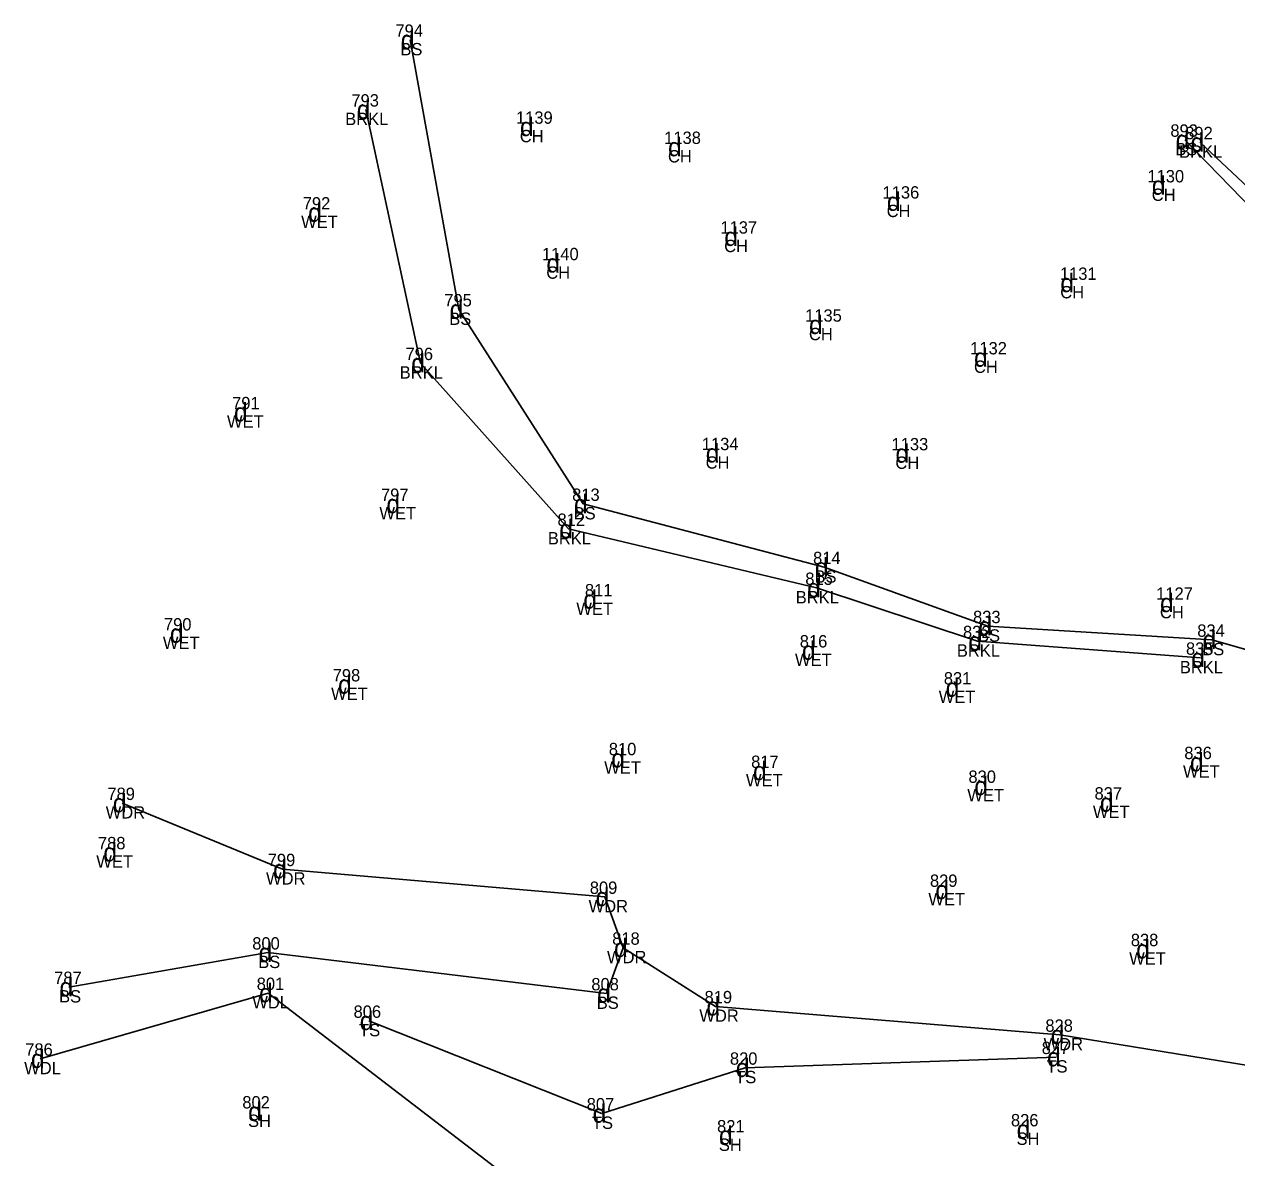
# Model space of a CAD drawing. Extents: x 17459 to 21139, y 33814 to 34251.
# Drawn here: x 17505 to 17701.5, y 34067.8 to 34251.5 of the extents above; entities that cross this region are included whole.
import ezdxf

# ---------------------------------------------------------------- set-up
doc = ezdxf.new("R2010")
doc.units = 0
for name, color, linetype in [('Level 14', 7, 'Continuous'), ('Level 16', 7, 'Continuous'), ('Level 17', 7, 'Continuous'), ('Level 46', 7, 'Continuous'), ('Level 47', 7, 'Continuous'), ('Level 48', 7, 'Continuous')]:
    doc.layers.add(name, color=color, linetype=linetype)

msp = doc.modelspace()

# ---------------------------------------------------------------- linework, layer by layer
at = {"layer": 'Level 14'}
for p, q in [((17520.81, 34125.28), (17546.8, 34114.57)), ((17546.8, 34114.57), (17599.08, 34110.07)), ((17599.08, 34110.07), (17602.06, 34101.83)), ((17602.06, 34101.83), (17617.03, 34092.34)), ((17507.54, 34083.85), (17544.51, 34094.5)), ((17544.51, 34094.5), (17594.09, 34056.45)), ((17617.03, 34092.34), (17672.83, 34087.73)), ((17672.83, 34087.73), (17725.88, 34079.05))]:
    msp.add_line(p, q, dxfattribs=at)
at = {"layer": 'Level 17'}
for p, q in [((17560.35, 34237.65), (17569.18, 34196.57)), ((17707.44, 34221.17), (17695.5, 34232.36)), ((17569.18, 34196.57), (17593.19, 34169.7)), ((17593.19, 34169.7), (17633.36, 34160.14)), ((17633.36, 34160.14), (17659.48, 34151.51)), ((17659.48, 34151.51), (17695.62, 34148.82))]:
    msp.add_line(p, q, dxfattribs=at)
at = {"layer": 'Level 48'}
for p, q in [((17567.49, 34248.95), (17575.41, 34205.27)), ((17706.46, 34218.93), (17693.09, 34232.76)), ((17575.41, 34205.27), (17595.57, 34173.75)), ((17595.57, 34173.75), (17634.61, 34163.5)), ((17634.61, 34163.5), (17661.12, 34153.94)), ((17661.12, 34153.94), (17697.45, 34151.73)), ((17697.45, 34151.73), (17739.75, 34139.78)), ((17599.32, 34094.44), (17602.06, 34101.83)), ((17512.17, 34095.47), (17544.44, 34101.05)), ((17544.44, 34101.05), (17599.32, 34094.44)), ((17560.83, 34089.99), (17598.57, 34074.99)), ((17621.79, 34082.39), (17672.24, 34084.12)), ((17598.57, 34074.99), (17621.79, 34082.39))]:
    msp.add_line(p, q, dxfattribs=at)

# ---------------------------------------------------------------- texts
at = {"layer": 'Level 16'}
for p in [(17550.97, 34219.47), (17538.95, 34187.1), (17563.66, 34172.25), (17595.57, 34156.78), (17528.56, 34151.25), (17631.01, 34148.5), (17555.82, 34143), (17654.31, 34142.5), (17600.1, 34131.04), (17693.9, 34130.41), (17623.08, 34128.98), (17658.95, 34126.56), (17679.3, 34123.86), (17517.78, 34115.8), (17652.63, 34109.71), (17685.18, 34100.1)]:
    msp.add_text('d', height=3, dxfattribs=at).set_placement(p)
at = {"layer": 'Level 46'}
for s, p in [('794', (17565.13, 34249.45)), ('BS', (17565.93, 34246.45)), ('793', (17557.99, 34238.15)), ('BRKL', (17556.99, 34235.15)), ('1139', (17584.67, 34235.36)), ('893', (17690.73, 34233.26)), ('CH', (17585.29, 34232.36)), ('1138', (17608.69, 34232.09)), ('892', (17693.14, 34232.86)), ('CH', (17609.3, 34229.09)), ('BS', (17691.53, 34230.26)), ('BRKL', (17692.15, 34229.86)), ('1130', (17687.01, 34225.86)), ('1136', (17644.08, 34223.24)), ('792', (17550.11, 34221.47)), ('CH', (17687.71, 34222.86)), ('CH', (17644.75, 34220.24)), ('WET', (17549.85, 34218.47)), ('1137', (17617.8, 34217.56)), ('1140', (17588.88, 34213.25)), ('CH', (17618.41, 34214.56)), ('CH', (17589.58, 34210.25)), ('1131', (17672.83, 34210.07)), ('795', (17573.05, 34205.77)), ('CH', (17672.88, 34207.07)), ('BS', (17573.85, 34202.77)), ('1135', (17631.53, 34203.29)), ('CH', (17632.15, 34200.29)), ('1132', (17658.29, 34197.99)), ('796', (17566.76, 34197.07)), ('BRKL', (17565.82, 34194.07)), ('CH', (17658.9, 34194.99)), ('791', (17538.66, 34189.1)), ('WET', (17537.83, 34186.1)), ('1134', (17614.79, 34182.47)), ('1133', (17645.54, 34182.44)), ('CH', (17615.41, 34179.47)), ('CH', (17646.16, 34179.44)), ('797', (17562.79, 34174.25)), ('813', (17593.77, 34174.25)), ('WET', (17562.53, 34171.25)), ('812', (17591.39, 34170.2)), ('BS', (17594.01, 34171.25)), ('BRKL', (17589.83, 34167.2)), ('814', (17632.82, 34164)), ('815', (17631.56, 34160.64)), ('BS', (17633.05, 34161)), ('811', (17595.84, 34158.78)), ('1127', (17688.43, 34158.22)), ('BRKL', (17630.01, 34157.64)), ('WET', (17594.45, 34155.78)), ('833', (17658.75, 34154.44)), ('CH', (17689.04, 34155.22)), ('790', (17527.61, 34153.25)), ('816', (17630.66, 34150.5)), ('832', (17657.12, 34152.01)), ('BS', (17659.56, 34151.44)), ('834', (17695.09, 34152.23)), ('WET', (17527.44, 34150.25)), ('BRKL', (17656.13, 34149.01)), ('835', (17693.26, 34149.32)), ('BS', (17695.89, 34149.23)), ('WET', (17629.89, 34147.5)), ('798', (17554.96, 34145)), ('831', (17654.01, 34144.5)), ('BRKL', (17692.27, 34146.32)), ('WET', (17554.7, 34142)), ('WET', (17653.19, 34141.5)), ('810', (17599.71, 34133.04)), ('817', (17622.78, 34130.98)), ('836', (17692.99, 34132.41)), ('WET', (17598.97, 34130.04)), ('WET', (17692.78, 34129.41)), ('WET', (17621.95, 34127.98)), ('830', (17658, 34128.56)), ('789', (17518.44, 34125.78)), ('WET', (17657.82, 34125.56)), ('837', (17678.44, 34125.86)), ('WET', (17678.18, 34122.86)), ('WDR', (17518.17, 34122.78)), ('788', (17516.91, 34117.8)), ('799', (17544.43, 34115.07)), ('WET', (17516.65, 34114.8)), ('WDR', (17544.16, 34112.07)), ('829', (17651.76, 34111.71)), ('809', (17596.63, 34110.57)), ('WDR', (17596.44, 34107.57)), ('WET', (17651.51, 34108.71)), ('800', (17541.92, 34101.55)), ('818', (17600.26, 34102.33)), ('838', (17684.32, 34102.1)), ('WDR', (17599.42, 34099.33)), ('BS', (17542.89, 34098.55)), ('WET', (17684.06, 34099.1)), ('787', (17509.81, 34095.97)), ('801', (17542.64, 34095)), ('808', (17596.88, 34094.94)), ('BS', (17510.61, 34092.97)), ('WDL', (17541.93, 34092)), ('BS', (17597.76, 34091.94)), ('819', (17615.23, 34092.84)), ('806', (17558.34, 34090.49)), ('WDR', (17614.39, 34089.84)), ('TS', (17559.24, 34087.49)), ('828', (17670.47, 34088.23)), ('786', (17505.12, 34084.35)), ('827', (17669.88, 34084.62)), ('WDR', (17670.19, 34085.23)), ('820', (17619.34, 34082.89)), ('TS', (17670.65, 34081.62)), ('WDL', (17504.95, 34081.35)), ('TS', (17620.2, 34079.89)), ('802', (17540.31, 34075.8)), ('807', (17596.13, 34075.49)), ('SH', (17541.24, 34072.8)), ('TS', (17596.98, 34072.49)), ('821', (17617.26, 34071.92)), ('826', (17664.89, 34072.9)), ('SH', (17665.8, 34069.9)), ('SH', (17617.55, 34068.92))]:
    msp.add_text(s, height=2, dxfattribs=at).set_placement(p)
at = {"layer": 'Level 47'}
for p in [(17565.99, 34247.45), (17558.85, 34236.15), (17585.3, 34233.36), (17609.31, 34230.09), (17691.59, 34231.26), (17694, 34230.86), (17687.72, 34223.86), (17644.77, 34221.24), (17618.43, 34215.56), (17589.59, 34211.25), (17672.89, 34208.07), (17573.91, 34203.77), (17632.16, 34201.29), (17567.68, 34195.07), (17658.91, 34195.99), (17615.42, 34180.47), (17646.17, 34180.44), (17594.07, 34172.25), (17591.69, 34168.2), (17633.11, 34162), (17631.86, 34158.64), (17689.05, 34156.22), (17659.62, 34152.44), (17657.98, 34150.01), (17695.95, 34150.23), (17694.12, 34147.32), (17519.31, 34123.78), (17545.3, 34113.07), (17597.58, 34108.57), (17600.56, 34100.33), (17542.94, 34099.55), (17510.67, 34093.97), (17543.01, 34093), (17597.82, 34092.94), (17615.53, 34090.84), (17559.33, 34088.49), (17671.33, 34086.23), (17670.74, 34082.62), (17506.04, 34082.35), (17620.29, 34080.89), (17541.25, 34073.8), (17597.07, 34073.49), (17665.81, 34070.9), (17617.56, 34069.92)]:
    msp.add_text('d', height=3, dxfattribs=at).set_placement(p)

doc.saveas('drawing.dxf')
